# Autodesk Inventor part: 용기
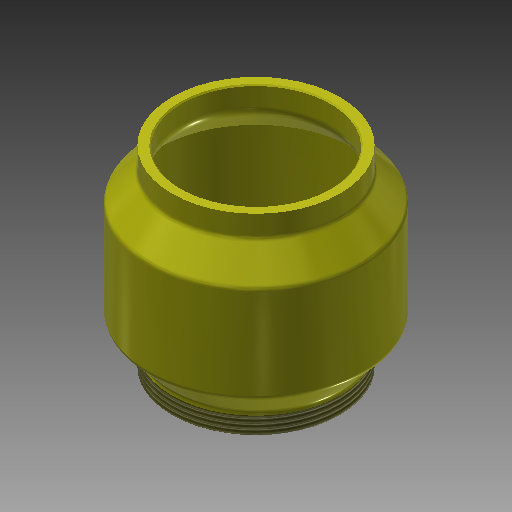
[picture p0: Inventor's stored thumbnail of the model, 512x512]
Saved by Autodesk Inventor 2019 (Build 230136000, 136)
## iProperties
Created: 2018-01
Part Number: 용기
Material: ABS 플라스틱
Document SubType Name: Modeling
Designer: mduedu
Density: 1 g/cm^3
Appearance: 노란색
Author: mduedu
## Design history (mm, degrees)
sketch "스케치1"
  geometry: L1 (0, 0)-(-35, 0); L2 (-35, 0)-(-35, 9); L3 (-35, 9)-(-45, 20); L4 (-45, 20)-(-45, 60); L5 (-45, 60)-(-35, 71); L6 (-35, 71)-(-35, 80); L7 (-35, 80)-(0, 80); L8 (0, 80)-(0, 0)
  constraints: 16 end point, 3 collinear, 3 parallel, 1 horizontal, 1 perpendicular
  dimensions: "d0" = 9 distance of L1.end L2.end; "d2" = 70 diameter of L2 L8; "d3" = 20 distance from line of L3.end L1; "d4" = 60 distance from line of L4.end L1; "d5" = 20 distance from line of L4.end L7; "d6" = 90 diameter of L4 L8
revolve "회전1" sketch "스케치1" stored, may be unused: angle "d7" = 90 deg
fillet "모깎기1" dims "d8" = 3
feature "쉘1" dims "d9" = 4
chamfer "모따기1" distance "d11" = 0.5; stored, may be unused: second distance "d12" = 2, angle "d13" = 45 deg
feature "스레드1" dims "d14" = 7, "d15" = 0
node "솔리드1"
